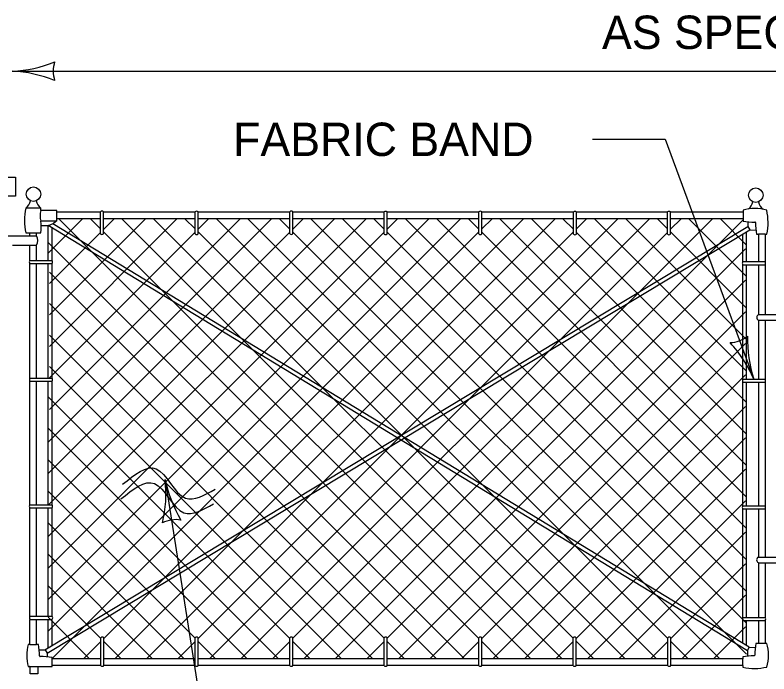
# Model space of a CAD drawing. Extents: x 49973.1 to 50021, y 49987.6 to 50015.4.
# Drawn here: x 50004.493 to 50005.847, y 49995.003 to 49996.187 of the extents above; entities that cross this region are included whole.
import ezdxf

# ---------------------------------------------------------------- set-up
doc = ezdxf.new("R2010")
doc.units = 0
for name, color, linetype in [('Level 1', 7, 'Continuous'), ('Level 2', 7, 'Continuous'), ('Level 3', 7, 'Continuous'), ('Level 6', 7, 'Continuous')]:
    doc.layers.add(name, color=color, linetype=linetype)

msp = doc.modelspace()

# ---------------------------------------------------------------- linework, layer by layer
at = {"layer": 'Level 1'}
for p, q in [((50004.5687, 49995.836), (50004.5395, 49995.836)), ((50004.5687, 49995.817), (50004.5687, 49995.836)), ((50004.6469, 49995.8331), (50004.5687, 49995.8331)), ((50004.6466, 49995.794), (50004.6466, 49995.8337)), ((50004.6521, 49995.794), (50004.6521, 49995.8337)), ((50004.817, 49995.8331), (50004.6521, 49995.8331)), ((50004.8169, 49995.7939), (50004.8169, 49995.8336)), ((50004.8224, 49995.7939), (50004.8224, 49995.8336)), ((50004.9864, 49995.8331), (50004.8224, 49995.8331)), ((50004.9867, 49995.794), (50004.9867, 49995.8337)), ((50005.1564, 49995.8331), (50004.992, 49995.8331)), ((50004.9922, 49995.794), (50004.9922, 49995.8337)), ((50005.1563, 49995.7937), (50005.1563, 49995.8334)), ((50005.1618, 49995.7937), (50005.1618, 49995.8334)), ((50005.3265, 49995.8331), (50005.1619, 49995.8331)), ((50005.3263, 49995.7939), (50005.3263, 49995.8336)), ((50005.4962, 49995.8331), (50005.3316, 49995.8331)), ((50005.3318, 49995.7939), (50005.3318, 49995.8336)), ((50005.4963, 49995.7934), (50005.4963, 49995.8331)), ((50005.6648, 49995.8331), (50005.5016, 49995.8331)), ((50005.5018, 49995.7934), (50005.5018, 49995.8331)), ((50005.6649, 49995.7936), (50005.6649, 49995.8333)), ((50005.6704, 49995.7936), (50005.6704, 49995.8333)), ((50005.8008, 49995.8331), (50005.6705, 49995.8331)), ((50005.8008, 49995.8367), (50005.8008, 49995.8328)), ((50005.8008, 49995.8328), (50005.8008, 49995.8208)), ((50004.5687, 49995.817), (50004.5395, 49995.817)), ((50004.5528, 49995.7593), (50004.6146, 49995.8211)), ((50004.5528, 49995.1371), (50005.2368, 49995.8211)), ((50004.5528, 49995.0805), (50005.2934, 49995.8211)), ((50004.5528, 49995.2501), (50005.1238, 49995.8211)), ((50004.5528, 49995.3067), (50005.0672, 49995.8211)), ((50004.5528, 49995.4199), (50004.954, 49995.8211)), ((50004.555, 49995.6483), (50004.7278, 49995.8211)), ((50004.555, 49995.5919), (50004.7842, 49995.8211)), ((50004.555, 49995.4787), (50004.8974, 49995.8211)), ((50004.5616, 49995.8123), (50004.5668, 49995.817)), ((50004.6466, 49995.8211), (50004.5687, 49995.8211)), ((50004.5721, 49995.8211), (50005.3261, 49995.0671)), ((50004.6287, 49995.8211), (50004.6466, 49995.8033)), ((50004.6521, 49995.802), (50004.6712, 49995.8211)), ((50004.8169, 49995.8211), (50004.6521, 49995.8211)), ((50004.6528, 49995.0672), (50005.4066, 49995.8211)), ((50004.6728, 49995.0307), (50005.4632, 49995.8211)), ((50004.6854, 49995.8211), (50005.4761, 49995.0307)), ((50004.742, 49995.8211), (50005.4957, 49995.0677)), ((50004.7986, 49995.8211), (50004.8169, 49995.8028)), ((50004.8224, 49995.8027), (50004.8408, 49995.8211)), ((50004.9869, 49995.8211), (50004.8224, 49995.8211)), ((50004.8224, 49995.0673), (50005.5762, 49995.8211)), ((50004.8424, 49995.0307), (50005.6328, 49995.8211)), ((50004.855, 49995.8211), (50005.6452, 49995.0307)), ((50004.9115, 49995.8211), (50005.6655, 49995.0673)), ((50004.9681, 49995.8211), (50004.9867, 49995.8025)), ((50005.1564, 49995.8211), (50004.992, 49995.8211)), ((50004.9922, 49995.8027), (50005.0106, 49995.8211)), ((50004.9922, 49995.0674), (50005.746, 49995.8211)), ((50005.0122, 49995.0307), (50005.8002, 49995.8187)), ((50005.0248, 49995.8211), (50005.8073, 49995.0389)), ((50005.0813, 49995.8211), (50005.8073, 49995.0948)), ((50005.1379, 49995.8211), (50005.1563, 49995.8027)), ((50005.1618, 49995.8027), (50005.1802, 49995.8211)), ((50005.3262, 49995.8211), (50005.1619, 49995.8211)), ((50005.1946, 49995.8211), (50005.8073, 49995.2081)), ((50005.251, 49995.8211), (50005.8073, 49995.2646)), ((50005.3076, 49995.8211), (50005.3263, 49995.8024)), ((50005.3318, 49995.8029), (50005.35, 49995.8211)), ((50005.4964, 49995.8211), (50005.3319, 49995.8211)), ((50005.3642, 49995.8211), (50005.8073, 49995.3778)), ((50005.4208, 49995.8211), (50005.8073, 49995.4344)), ((50005.4774, 49995.8211), (50005.4963, 49995.8022)), ((50005.5018, 49995.8033), (50005.5196, 49995.8211)), ((50005.665, 49995.8211), (50005.5019, 49995.8211)), ((50005.534, 49995.8211), (50005.8073, 49995.5476)), ((50005.5904, 49995.8211), (50005.8073, 49995.604)), ((50005.647, 49995.8211), (50005.6649, 49995.8033)), ((50005.8006, 49995.8211), (50005.6704, 49995.8211)), ((50005.6705, 49995.8022), (50005.6894, 49995.8211)), ((50005.7036, 49995.8211), (50005.8073, 49995.7172)), ((50005.7602, 49995.8211), (50005.8073, 49995.7739)), ((50005.8008, 49995.8208), (50005.8008, 49995.8169)), ((50004.5405, 49995.8093), (50004.5533, 49995.8091)), ((50004.5471, 49995.0465), (50005.8094, 49995.807)), ((50004.5528, 49995.7462), (50004.5528, 49995.8091)), ((50005.8087, 49995.0451), (50004.5529, 49995.8091)), ((50004.5533, 49995.8091), (50004.5616, 49995.8123)), ((50004.5598, 49995.7463), (50004.5598, 49995.805)), ((50005.8118, 49995.0514), (50004.5615, 49995.8122)), ((50005.8094, 49995.8156), (50005.8094, 49995.807)), ((50005.8094, 49995.807), (50005.8132, 49995.8011)), ((50004.4485, 49995.7903), (50004.5322, 49995.7903)), ((50004.5129, 49995.7956), (50004.5397, 49995.7956)), ((50004.5202, 49995.7903), (50004.5202, 49995.7956)), ((50004.5322, 49995.7903), (50004.5322, 49995.7956)), ((50004.5509, 49995.0406), (50005.8132, 49995.8011)), ((50004.5528, 49995.1937), (50005.1563, 49995.7972)), ((50004.5528, 49995.3633), (50004.9867, 49995.7972)), ((50004.555, 49995.5353), (50004.8169, 49995.7972)), ((50004.555, 49995.7049), (50004.6466, 49995.7965)), ((50004.5596, 49995.0307), (50005.3263, 49995.7974)), ((50004.6521, 49995.7978), (50005.4196, 49995.0307)), ((50004.7292, 49995.0307), (50005.4963, 49995.7978)), ((50004.8224, 49995.7974), (50005.5894, 49995.0307)), ((50004.899, 49995.0307), (50005.6649, 49995.7966)), ((50004.9922, 49995.7971), (50005.7589, 49995.0307)), ((50005.1618, 49995.7972), (50005.8073, 49995.1517)), ((50005.3318, 49995.7969), (50005.8073, 49995.3211)), ((50005.5018, 49995.7967), (50005.8073, 49995.4909)), ((50005.6704, 49995.7977), (50005.8073, 49995.6605)), ((50005.8003, 49995.7438), (50005.8003, 49995.7934)), ((50005.8073, 49995.7441), (50005.8073, 49995.7976)), ((50005.8132, 49995.8011), (50005.8239, 49995.8009)), ((50005.8251, 49995.7932), (50005.8284, 49995.7932)), ((50005.8404, 49995.7932), (50005.8284, 49995.7932)), ((50005.8284, 49995.7932), (50005.8284, 49995.7441)), ((50005.8404, 49995.7932), (50005.8436, 49995.7932)), ((50005.8404, 49995.7932), (50005.8404, 49995.744)), ((50004.5528, 49995.7782), (50005.3003, 49995.0307)), ((50004.4887, 49995.7738), (50004.5322, 49995.7738)), ((50004.5202, 49995.7462), (50004.5202, 49995.7738)), ((50004.5322, 49995.7462), (50004.5322, 49995.7738)), ((50005.0686, 49995.0307), (50005.805, 49995.7671)), ((50004.5201, 49995.7462), (50004.5598, 49995.7462)), ((50004.5201, 49995.7407), (50004.5598, 49995.7407)), ((50004.5202, 49995.5349), (50004.5202, 49995.7407)), ((50004.5322, 49995.535), (50004.5322, 49995.7407)), ((50004.5528, 49995.5349), (50004.5528, 49995.7407)), ((50004.5598, 49995.535), (50004.5598, 49995.7407)), ((50005.8003, 49995.5323), (50005.8003, 49995.739)), ((50005.8006, 49995.7441), (50005.8403, 49995.7441)), ((50005.8006, 49995.7386), (50005.8403, 49995.7386)), ((50005.8073, 49995.5328), (50005.8073, 49995.7386)), ((50005.8284, 49995.7386), (50005.8284, 49995.6489)), ((50005.8404, 49995.7388), (50005.8404, 49995.6489)), ((50004.555, 49995.7253), (50005.2501, 49995.0307)), ((50005.1618, 49995.0674), (50005.805, 49995.7105)), ((50004.555, 49995.6687), (50005.1563, 49995.0675)), ((50005.1818, 49995.0307), (50005.805, 49995.6539)), ((50005.8284, 49995.6489), (50005.8712, 49995.6489)), ((50005.8284, 49995.6389), (50005.8712, 49995.6389)), ((50005.8284, 49995.6389), (50005.8284, 49995.5328)), ((50005.8404, 49995.6389), (50005.8404, 49995.5328)), ((50004.555, 49995.6121), (50005.1362, 49995.0307)), ((50005.2384, 49995.0307), (50005.805, 49995.5973)), ((50004.555, 49995.5555), (50005.0796, 49995.0307)), ((50004.5202, 49995.5349), (50004.5599, 49995.5349)), ((50005.3316, 49995.0673), (50005.805, 49995.5407)), ((50005.8008, 49995.5328), (50005.8404, 49995.5328)), ((50004.5202, 49995.5294), (50004.5599, 49995.5294)), ((50004.5202, 49995.3074), (50004.5202, 49995.5294)), ((50004.5322, 49995.3074), (50004.5322, 49995.5294)), ((50004.5528, 49995.3074), (50004.5528, 49995.5294)), ((50004.5598, 49995.3074), (50004.5598, 49995.5295)), ((50005.8003, 49995.305), (50005.8003, 49995.5278)), ((50005.8007, 49995.5273), (50005.8404, 49995.5273)), ((50005.8073, 49995.3053), (50005.8073, 49995.5273)), ((50005.8284, 49995.5273), (50005.8284, 49995.3053)), ((50005.8404, 49995.5273), (50005.8404, 49995.3052)), ((50004.5528, 49995.5013), (50004.9867, 49995.0672)), ((50005.3516, 49995.0307), (50005.805, 49995.4841)), ((50004.5528, 49995.4447), (50004.9666, 49995.0307)), ((50005.4082, 49995.0307), (50005.805, 49995.4275)), ((50004.5528, 49995.3881), (50004.91, 49995.0307)), ((50005.5012, 49995.0673), (50005.805, 49995.3711)), ((50004.5528, 49995.3315), (50004.8169, 49995.0674)), ((50004.5201, 49995.3074), (50004.5598, 49995.3074)), ((50004.5201, 49995.3019), (50004.5598, 49995.3019)), ((50004.5202, 49995.1071), (50004.5202, 49995.3018)), ((50004.5322, 49995.107), (50004.5322, 49995.3018)), ((50004.5528, 49995.1069), (50004.5528, 49995.3018)), ((50004.5598, 49995.1069), (50004.5598, 49995.3019)), ((50005.5212, 49995.0307), (50005.805, 49995.3145)), ((50005.8006, 49995.3053), (50005.8403, 49995.3053)), ((50005.8003, 49995.1043), (50005.8003, 49995.3002)), ((50005.8006, 49995.2998), (50005.8403, 49995.2998)), ((50005.8073, 49995.1049), (50005.8073, 49995.2998)), ((50005.8284, 49995.2998), (50005.8284, 49995.2133)), ((50005.8404, 49995.3), (50005.8404, 49995.2133)), ((50004.5528, 49995.275), (50004.797, 49995.0307)), ((50005.5778, 49995.0307), (50005.805, 49995.2579)), ((50004.5528, 49995.2183), (50004.7404, 49995.0307)), ((50005.8281, 49995.2133), (50005.8709, 49995.2133)), ((50005.671, 49995.0672), (50005.805, 49995.2013)), ((50005.8281, 49995.2033), (50005.8709, 49995.2033)), ((50005.8284, 49995.2033), (50005.8284, 49995.1049)), ((50005.8404, 49995.2033), (50005.8404, 49995.1049)), ((50004.5528, 49995.1617), (50004.6473, 49995.0672)), ((50005.691, 49995.0307), (50005.805, 49995.1447)), ((50004.5202, 49995.0563), (50004.5202, 49995.1015)), ((50004.5203, 49995.107), (50004.56, 49995.107)), ((50004.5203, 49995.1015), (50004.56, 49995.1015)), ((50004.5322, 49995.0563), (50004.5322, 49995.1014)), ((50004.5528, 49995.1051), (50004.6272, 49995.0307)), ((50004.5528, 49995.0499), (50004.5528, 49995.1014)), ((50004.5598, 49995.0542), (50004.5598, 49995.1014)), ((50005.8003, 49995.0584), (50005.8003, 49995.1001)), ((50005.8008, 49995.1049), (50005.8405, 49995.1049)), ((50005.8008, 49995.0994), (50005.8405, 49995.0994)), ((50005.8073, 49995.0542), (50005.8073, 49995.0994)), ((50005.8284, 49995.0994), (50005.8284, 49995.0583)), ((50005.8404, 49995.0994), (50005.8404, 49995.0583)), ((50005.7476, 49995.0307), (50005.805, 49995.0881)), ((50004.6162, 49995.0307), (50004.6473, 49995.0618)), ((50004.6473, 49995.0182), (50004.6473, 49995.0684)), ((50004.6528, 49995.0182), (50004.6528, 49995.0684)), ((50004.6528, 49995.0617), (50004.6838, 49995.0307)), ((50004.7858, 49995.0307), (50004.8169, 49995.0618)), ((50004.8169, 49995.0182), (50004.8169, 49995.0684)), ((50004.8224, 49995.0182), (50004.8224, 49995.0684)), ((50004.8224, 49995.0619), (50004.8535, 49995.0307)), ((50004.9556, 49995.0307), (50004.9867, 49995.0618)), ((50004.9867, 49995.0182), (50004.9867, 49995.0684)), ((50004.9922, 49995.0182), (50004.9922, 49995.0684)), ((50004.9922, 49995.0618), (50005.0232, 49995.0307)), ((50005.1252, 49995.0307), (50005.1563, 49995.0618)), ((50005.1563, 49995.0182), (50005.1563, 49995.0684)), ((50005.1618, 49995.0182), (50005.1618, 49995.0684)), ((50005.1618, 49995.0619), (50005.193, 49995.0307)), ((50005.295, 49995.0307), (50005.3261, 49995.0618)), ((50005.3261, 49995.0182), (50005.3261, 49995.0684)), ((50005.3316, 49995.0182), (50005.3316, 49995.0684)), ((50005.3316, 49995.0616), (50005.3625, 49995.0307)), ((50005.4646, 49995.0307), (50005.4957, 49995.0618)), ((50005.4957, 49995.0182), (50005.4957, 49995.0684)), ((50005.5012, 49995.0182), (50005.5012, 49995.0684)), ((50005.5012, 49995.0621), (50005.5327, 49995.0307)), ((50005.6344, 49995.0307), (50005.6655, 49995.0617)), ((50005.6655, 49995.0182), (50005.6655, 49995.0684)), ((50005.671, 49995.0182), (50005.671, 49995.0684)), ((50005.671, 49995.0618), (50005.7022, 49995.0307)), ((50005.8279, 49995.0583), (50005.824, 49995.0583)), ((50005.8399, 49995.0583), (50005.8279, 49995.0583)), ((50005.8438, 49995.0583), (50005.8399, 49995.0583)), ((50004.5202, 49995.0563), (50004.517, 49995.0563)), ((50004.5202, 49995.0563), (50004.5322, 49995.0563)), ((50004.5355, 49995.0563), (50004.5322, 49995.0563)), ((50004.5369, 49995.0465), (50004.5472, 49995.0465)), ((50004.5472, 49995.0465), (50004.551, 49995.0406)), ((50005.8087, 49995.0451), (50005.8118, 49995.0514)), ((50005.8087, 49995.0451), (50005.8087, 49995.0353)), ((50005.8118, 49995.0514), (50005.8228, 49995.0512)), ((50004.551, 49995.0406), (50004.5511, 49995.034)), ((50004.5598, 49995.0287), (50004.5598, 49995.0326)), ((50005.8003, 49995.034), (50005.8003, 49995.0307)), ((50004.6473, 49995.0307), (50004.5597, 49995.0307)), ((50004.6473, 49995.0187), (50004.5597, 49995.0187)), ((50004.5598, 49995.0167), (50004.5598, 49995.0287)), ((50004.8169, 49995.0307), (50004.6528, 49995.0307)), ((50004.8169, 49995.0187), (50004.6528, 49995.0187)), ((50004.9867, 49995.0307), (50004.8224, 49995.0307)), ((50004.9867, 49995.0187), (50004.8224, 49995.0187)), ((50005.1563, 49995.0307), (50004.9922, 49995.0307)), ((50005.1563, 49995.0187), (50004.9922, 49995.0187)), ((50005.3261, 49995.0307), (50005.1618, 49995.0307)), ((50005.3261, 49995.0187), (50005.1618, 49995.0187)), ((50005.4957, 49995.0307), (50005.3316, 49995.0307)), ((50005.4957, 49995.0187), (50005.3316, 49995.0187)), ((50005.6655, 49995.0307), (50005.5012, 49995.0307)), ((50005.6655, 49995.0187), (50005.5012, 49995.0187)), ((50005.8003, 49995.0307), (50005.671, 49995.0307)), ((50005.8003, 49995.0187), (50005.671, 49995.0187)), ((50005.8003, 49995.0187), (50005.8003, 49995.0307)), ((50005.8003, 49995.0187), (50005.8003, 49995.0155)), ((50004.517, 49995.0167), (50004.5598, 49995.0167)), ((50004.5202, 49995.0167), (50004.5192, 49995.0167))]:
    msp.add_line(p, q, dxfattribs=at)
for points in [[(50004.4942, 49995.8961), (50004.4942, 49995.8618), (50004.4433, 49995.8618), (50004.4433, 49995.8961)], [(50004.5203, 49995.0035), (50004.5203, 49995.0165), (50004.5344, 49995.0165), (50004.5344, 49995.0035)]]:
    msp.add_lwpolyline(points, close=True, dxfattribs=at)
msp.add_lwpolyline([(50004.5395, 49995.836), (50004.5395, 49995.8402), (50004.5129, 49995.8402)], dxfattribs=at)
for centre in [(50004.5265, 49995.8653), (50005.8237, 49995.8635)]:
    msp.add_circle(centre, 0.013, dxfattribs=at)
for centre, radius, start, end in [((50004.5016, 49995.8564), 0.0197, 305.1337, 351.7381), ((50004.5508, 49995.8564), 0.0197, 188.9769, 234.8663), ((50005.7988, 49995.8546), 0.0197, 306.5272, 351.7381), ((50005.848, 49995.8546), 0.0197, 188.9769, 236.2764), ((50004.611, 49995.8179), 0.1006, 167.1929, 192.8056), ((50004.584, 49995.8265), 0.0455, 167.94, 192.0471), ((50004.6494, 49995.8305), 0.00424, 49.8072, 130.5105), ((50004.8197, 49995.8304), 0.00424, 49.8072, 130.5105), ((50004.9895, 49995.8305), 0.00424, 49.8072, 130.5105), ((50005.1591, 49995.8302), 0.00424, 49.8072, 130.5105), ((50005.3291, 49995.8304), 0.00424, 49.8072, 130.5105), ((50005.4991, 49995.8299), 0.00424, 49.8072, 130.5105), ((50005.6677, 49995.8301), 0.00424, 49.8072, 130.5105), ((50005.8221, 49995.7572), 0.0823, 74.999, 105.0029), ((50005.7429, 49995.8145), 0.1029, 348.0613, 12.47), ((50004.483, 49995.8058), 0.0576, 349.8438, 11.2436), ((50005.8187, 49995.9039), 0.0888, 258.3626, 272.1883), ((50005.8224, 49995.8143), 0.000958, 349.4816, 109.6717), ((50005.9156, 49995.8113), 0.0923, 178.2536, 191.2832), ((50004.5178, 49995.7821), 0.0166, 330.1626, 29.8393), ((50004.6493, 49995.797), 0.00408, 227.6835, 312.675), ((50004.8196, 49995.7969), 0.00408, 227.6835, 312.675), ((50004.9894, 49995.797), 0.00408, 227.6835, 312.675), ((50005.159, 49995.7967), 0.00408, 227.6835, 312.675), ((50005.329, 49995.7969), 0.00408, 227.6835, 312.675), ((50005.499, 49995.7964), 0.00408, 227.6835, 312.675), ((50005.6676, 49995.7966), 0.00408, 227.6835, 312.675), ((50004.5231, 49995.7435), 0.00408, 137.6835, 222.675), ((50004.5566, 49995.7435), 0.00424, 319.8072, 40.5105), ((50005.8036, 49995.7414), 0.00408, 137.981, 222.675), ((50005.8371, 49995.7414), 0.00424, 319.8072, 40.7421), ((50005.8311, 49995.6439), 0.00567, 118.1722, 241.7896), ((50004.5232, 49995.5322), 0.00408, 137.6835, 222.675), ((50004.5567, 49995.5322), 0.00424, 319.8072, 40.5105), ((50005.8035, 49995.5301), 0.00393, 135.1005, 223.8252), ((50005.8372, 49995.5301), 0.00424, 319.8072, 40.7421), ((50004.5231, 49995.3047), 0.00408, 137.6835, 222.675), ((50004.5566, 49995.3047), 0.00424, 319.8072, 40.5105), ((50005.8036, 49995.3026), 0.00408, 137.981, 222.675), ((50005.8371, 49995.3026), 0.00424, 319.8072, 40.7421), ((50005.8308, 49995.2083), 0.00567, 118.0389, 241.7896), ((50004.5233, 49995.1043), 0.00408, 137.6835, 222.675), ((50004.5568, 49995.1043), 0.00424, 319.8072, 40.5105), ((50005.8038, 49995.1022), 0.00408, 137.6835, 222.675), ((50005.8373, 49995.1022), 0.00424, 319.8072, 40.7421), ((50004.65, 49995.0652), 0.00424, 49.4895, 130.1928), ((50004.8196, 49995.0652), 0.00424, 49.4895, 130.1928), ((50004.9894, 49995.0652), 0.00424, 49.4895, 130.1928), ((50005.159, 49995.0652), 0.00424, 49.4895, 130.1928), ((50005.3288, 49995.0652), 0.00424, 49.4895, 130.1928), ((50005.4984, 49995.0652), 0.00424, 49.4895, 130.1928), ((50005.6682, 49995.0652), 0.00424, 49.4895, 130.1928), ((50005.9109, 49995.0404), 0.0888, 168.3626, 182.0358), ((50005.7643, 49995.037), 0.0823, 344.999, 15.0029), ((50004.5938, 49995.0365), 0.0793, 165.5423, 194.4548), ((50004.445, 49995.0383), 0.0923, 358.48, 11.2832), ((50004.5393, 49995.0364), 0.00206, 195.7264, 250.6739), ((50004.5419, 49994.9457), 0.0888, 78.3626, 92.1259), ((50005.8184, 49994.9436), 0.0923, 88.5988, 101.2832), ((50005.8202, 49995.0378), 0.00206, 280.2386, 344.6517), ((50004.6501, 49995.0212), 0.00408, 227.325, 312.3165), ((50004.8197, 49995.0212), 0.00408, 227.325, 312.3165), ((50004.9895, 49995.0212), 0.00408, 227.325, 312.3165), ((50005.1591, 49995.0212), 0.00408, 227.325, 312.3165), ((50005.3289, 49995.0212), 0.00408, 227.325, 312.3165), ((50005.4985, 49995.0212), 0.00408, 227.325, 312.3165), ((50005.6683, 49995.0212), 0.00408, 227.325, 312.3165), ((50005.8216, 49995.1162), 0.1029, 258.0613, 282.47)]:
    msp.add_arc(centre, radius, start, end, dxfattribs=at)
at = {"layer": 'Level 3'}
for p, q in [((50004.4885, 49996.0861), (50007.2582, 49996.0861)), ((50005.5303, 49995.9638), (50005.6607, 49995.9638)), ((50005.6607, 49995.9638), (50005.82, 49995.5332)), ((50004.763, 49995.3524), (50004.8541, 49994.77))]:
    msp.add_line(p, q, dxfattribs=at)
for centre, radius, start, end in [((50004.477, 49996.3188), 0.233, 272.8273, 292.0772), ((50004.6167, 49996.0861), 0.0548, 162.1388, 197.8612), ((50004.4793, 49995.864), 0.2223, 67.456, 87.6395), ((50005.7749, 49995.6533), 0.0548, 272.7096, 308.432), ((50006.0312, 49995.6027), 0.2223, 178.0268, 198.2103), ((50005.6062, 49995.4407), 0.233, 23.3981, 42.648), ((50004.5421, 49995.3272), 0.2223, 346.3452, 6.5287), ((50004.9911, 49995.3998), 0.233, 191.7165, 210.9664), ((50004.7828, 49995.2258), 0.0548, 81.028, 116.7504)]:
    msp.add_arc(centre, radius, start, end, dxfattribs=at)
at = {"layer": 'Level 6'}
for points in [[(50004.6864, 49995.3441), (50004.7466, 49995.372), (50004.7996, 49995.3192), (50004.8525, 49995.3353)], [(50004.6835, 49995.3177), (50004.7437, 49995.3456), (50004.7967, 49995.2928), (50004.8496, 49995.3089)]]:
    msp.add_spline(points, degree=3, dxfattribs=at)

# ---------------------------------------------------------------- texts
at = {"layer": 'Level 2'}
for s, p in [('AS SPECIFIED', (50005.5475, 49996.1261)), ('FABRIC BAND', (50004.8851, 49995.9338))]:
    msp.add_text(s, height=0.06, dxfattribs=at).set_placement(p)

doc.saveas('drawing.dxf')
